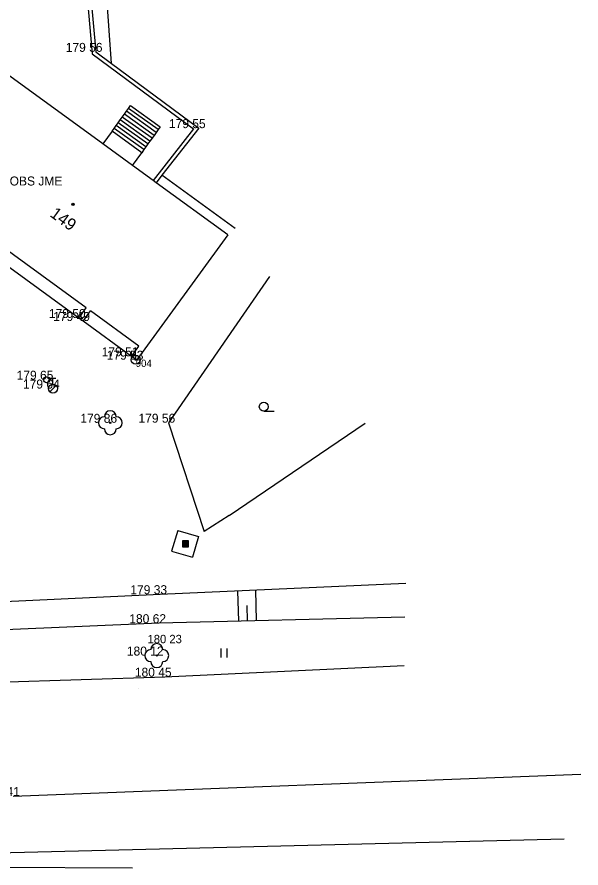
# Model space of a CAD drawing. Extents: x -537755 to -537431, y -1180722 to -1180510.
# Drawn here: x -537478.3 to -537431.3, y -1180722.3 to -1180651.3 of the extents above; entities that cross this region are included whole.
import ezdxf

# ---------------------------------------------------------------- set-up
doc = ezdxf.new("R2010")
doc.units = 0
for name, color, linetype in [('Vrstva 1', 7, 'Continuous'), ('Vrstva 11', 7, 'Continuous'), ('Vrstva 14', 7, 'Continuous'), ('Vrstva 15', 7, 'Continuous'), ('Vrstva 21', 7, 'Continuous'), ('Vrstva 22', 7, 'Continuous'), ('Vrstva 23', 7, 'Continuous'), ('Vrstva 25', 7, 'Continuous'), ('Vrstva 28', 7, 'Continuous'), ('Vrstva 3', 7, 'Continuous'), ('Vrstva 36', 7, 'Continuous'), ('Vrstva 39', 7, 'Continuous'), ('Vrstva 41', 7, 'Continuous'), ('Vrstva 47', 7, 'Continuous'), ('Vrstva 5', 7, 'Continuous'), ('Vrstva 7', 7, 'Continuous'), ('Vrstva 8', 7, 'Continuous')]:
    doc.layers.add(name, color=color, linetype=linetype)

msp = doc.modelspace()

# ---------------------------------------------------------------- linework, layer by layer
at = {"layer": 'Vrstva 1'}
for p, q in [((-537471.77, -1180654.18), (-537471.77, -1180654.18)), ((-537470.39, -1180660.8), (-537470.39, -1180660.8)), ((-537466.39, -1180660.44), (-537466.39, -1180660.44)), ((-537463.16, -1180660.55), (-537463.16, -1180660.55)), ((-537467.93, -1180662.6), (-537467.93, -1180662.6)), ((-537466.25, -1180664.49), (-537466.25, -1180664.49)), ((-537473.18, -1180676.41), (-537473.18, -1180676.41)), ((-537472.82, -1180676.66), (-537472.82, -1180676.66)), ((-537468.77, -1180679.61), (-537468.77, -1180679.61)), ((-537468.35, -1180679.89), (-537468.35, -1180679.89)), ((-537475.87, -1180681.56), (-537475.87, -1180681.56)), ((-537475.34, -1180682.3), (-537475.34, -1180682.3)), ((-537470.55, -1180685.16), (-537470.55, -1180685.16)), ((-537465.7, -1180685.15), (-537465.7, -1180685.15)), ((-537472.94, -1180699.79), (-537472.94, -1180699.79)), ((-537466.378, -1180699.474), (-537466.378, -1180699.474)), ((-537473.04, -1180701.98), (-537473.04, -1180701.98)), ((-537466.466, -1180701.894), (-537466.466, -1180701.894)), ((-537465.11, -1180703.57), (-537465.11, -1180703.57)), ((-537466.67, -1180704.6), (-537466.67, -1180704.6)), ((-537466.003, -1180706.367), (-537466.003, -1180706.367)), ((-537468.22, -1180707.37), (-537468.22, -1180707.37))]:
    msp.add_line(p, q, dxfattribs=at)
at = {"layer": 'Vrstva 11'}
for p, q in [((-537473.149, -1180641.864), (-537472.067, -1180654.346)), ((-537472.067, -1180654.346), (-537463.601, -1180660.61)), ((-537466.899, -1180661.153), (-537469.38, -1180659.384)), ((-537466.729, -1180660.916), (-537469.211, -1180659.146)), ((-537466.56, -1180660.678), (-537469.041, -1180658.908)), ((-537467.407, -1180661.867), (-537469.889, -1180660.097)), ((-537467.238, -1180661.629), (-537469.719, -1180659.859)), ((-537467.068, -1180661.391), (-537469.55, -1180659.622)), ((-537467.746, -1180662.342), (-537470.228, -1180660.573)), ((-537467.577, -1180662.104), (-537470.058, -1180660.335)), ((-537463.601, -1180660.61), (-537466.983, -1180664.922)), ((-537460.141, -1180668.942), (-537466.25, -1180664.49)), ((-537464.922, -1180694.166), (-537463.182, -1180694.658)), ((-537463.182, -1180694.658), (-537463.698, -1180696.382))]:
    msp.add_line(p, q, dxfattribs=at)
for points in [[(-537470.39, -1180660.8), (-537470.228, -1180660.573), (-537470.058, -1180660.335), (-537469.889, -1180660.097), (-537469.719, -1180659.859), (-537469.55, -1180659.622), (-537469.38, -1180659.384), (-537469.211, -1180659.146), (-537469.041, -1180658.908), (-537468.872, -1180658.671), (-537466.39, -1180660.44), (-537466.56, -1180660.678), (-537466.729, -1180660.916), (-537466.899, -1180661.153), (-537467.068, -1180661.391), (-537467.238, -1180661.629), (-537467.407, -1180661.867), (-537467.577, -1180662.104), (-537467.746, -1180662.342), (-537467.93, -1180662.6)], [(-537468.707, -1180663.666), (-537467.93, -1180662.6), (-537470.39, -1180660.8), (-537471.17, -1180661.871)], [(-537464.922, -1180694.166), (-537465.438, -1180695.89), (-537463.698, -1180696.382)]]:
    msp.add_lwpolyline(points, dxfattribs=at)
at = {"layer": 'Vrstva 14'}
for p, q in [((-537466.378, -1180699.474), (-537445.876, -1180698.559)), ((-537486.861, -1180700.435), (-537466.378, -1180699.474)), ((-537445.969, -1180701.386), (-537466.466, -1180701.894)), ((-537466.466, -1180701.894), (-537486.999, -1180702.764)), ((-537466.003, -1180706.367), (-537446.015, -1180705.434)), ((-537483.645, -1180706.944), (-537466.003, -1180706.367)), ((-537478.67, -1180716.34), (-537431.26, -1180714.51)), ((-537432.66, -1180719.92), (-537480.74, -1180721.12)), ((-537500.95, -1180722.15), (-537468.69, -1180722.34))]:
    msp.add_line(p, q, dxfattribs=at)
at = {"layer": 'Vrstva 15'}
for p, q in [((-537459.926, -1180699.186), (-537459.862, -1180701.73)), ((-537458.427, -1180699.119), (-537458.363, -1180701.693)), ((-537459.144, -1180700.431), (-537459.113, -1180701.712))]:
    msp.add_line(p, q, dxfattribs=at)
at = {"layer": 'Vrstva 21'}
for radius in [0.375, 0.05]:
    msp.add_circle((-537468.43, -1180679.89), radius, dxfattribs=at)
at = {"layer": 'Vrstva 22'}
for centre in [(-537470.55, -1180685.16), (-537466.67, -1180704.6)]:
    msp.add_circle(centre, 0.05, dxfattribs=at)
for centre, start, end in [((-537470.55, -1180684.66), 0, 180), ((-537471.05, -1180685.16), 90, 270), ((-537470.05, -1180685.16), 270, 90), ((-537470.55, -1180685.66), 180, 0), ((-537466.67, -1180704.1), 0, 180), ((-537467.17, -1180704.6), 90, 270), ((-537466.17, -1180704.6), 270, 90), ((-537466.67, -1180705.1), 180, 0)]:
    msp.add_arc(centre, 0.5, start, end, dxfattribs=at)
at = {"layer": 'Vrstva 25'}
for points in [[(-537464.517, -1180695.517), (-537464.017, -1180695.517), (-537464.017, -1180695.017), (-537464.517, -1180695.017)], [(-537464.467, -1180695.467), (-537464.067, -1180695.467), (-537464.067, -1180695.067), (-537464.467, -1180695.067)], [(-537464.417, -1180695.417), (-537464.117, -1180695.417), (-537464.117, -1180695.117), (-537464.417, -1180695.117)], [(-537464.367, -1180695.367), (-537464.167, -1180695.367), (-537464.167, -1180695.167), (-537464.367, -1180695.167)], [(-537464.317, -1180695.317), (-537464.217, -1180695.317), (-537464.217, -1180695.217), (-537464.317, -1180695.217)]]:
    msp.add_lwpolyline(points, close=True, dxfattribs=at)
at = {"layer": 'Vrstva 28'}
for p, q in [((-537475.59, -1180681.425), (-537475.09, -1180681.425)), ((-537475.34, -1180681.925), (-537475.34, -1180681.425)), ((-537475.598, -1180682.572), (-537475.068, -1180682.042))]:
    msp.add_line(p, q, dxfattribs=at)
for centre, radius in [((-537475.87, -1180681.56), 0.25), ((-537475.34, -1180682.3), 0.375)]:
    msp.add_circle(centre, radius, dxfattribs=at)
at = {"layer": 'Vrstva 36'}
for p, q in [((-537457.736, -1180684.192), (-537456.861, -1180684.192)), ((-537461.296, -1180704.773), (-537461.296, -1180704.023)), ((-537460.796, -1180704.773), (-537460.796, -1180704.023))]:
    msp.add_line(p, q, dxfattribs=at)
msp.add_circle((-537457.736, -1180683.817), 0.375, dxfattribs=at)
at = {"layer": 'Vrstva 39'}
for radius in [0.09, 0.0398]:
    msp.add_circle((-537473.67, -1180666.92), radius, dxfattribs=at)
at = {"layer": 'Vrstva 5'}
for p, q in [((-537471.17, -1180661.871), (-537479.24, -1180655.98)), ((-537468.707, -1180663.666), (-537471.17, -1180661.871)), ((-537472.568, -1180675.569), (-537481.448, -1180669.099)), ((-537460.746, -1180669.452), (-537468.35, -1180679.89)), ((-537473.18, -1180676.41), (-537482.06, -1180669.94)), ((-537473.18, -1180676.41), (-537472.568, -1180675.569)), ((-537472.82, -1180676.66), (-537472.208, -1180675.819)), ((-537468.158, -1180678.769), (-537472.208, -1180675.819)), ((-537472.82, -1180676.66), (-537473.18, -1180676.41)), ((-537468.77, -1180679.61), (-537472.82, -1180676.66)), ((-537468.77, -1180679.61), (-537468.158, -1180678.769)), ((-537468.35, -1180679.89), (-537468.77, -1180679.61))]:
    msp.add_line(p, q, dxfattribs=at)
for points in [[(-537466.983, -1180664.922), (-537468.707, -1180663.666)], [(-537466.732, -1180665.105), (-537466.983, -1180664.922)], [(-537460.746, -1180669.452), (-537466.732, -1180665.105)]]:
    msp.add_lwpolyline(points, dxfattribs=at)
at = {"layer": 'Vrstva 7'}
for p, q in [((-537470.445, -1180655.161), (-537472.08, -1180632.29)), ((-537472.84, -1180641.84), (-537471.77, -1180654.18)), ((-537471.77, -1180654.18), (-537470.445, -1180655.161)), ((-537470.445, -1180655.161), (-537463.16, -1180660.55)), ((-537463.16, -1180660.55), (-537466.25, -1180664.49)), ((-537466.25, -1180664.49), (-537466.732, -1180665.105)), ((-537457.256, -1180672.939), (-537465.7, -1180685.15)), ((-537465.7, -1180685.15), (-537462.728, -1180694.25)), ((-537460.64, -1180692.9), (-537449.283, -1180685.191))]:
    msp.add_line(p, q, dxfattribs=at)
at = {"layer": 'Vrstva 8'}
msp.add_line((-537460.64, -1180692.9), (-537462.728, -1180694.25), dxfattribs=at)

# ---------------------------------------------------------------- texts
at = {"layer": 'Vrstva 23'}
msp.add_text('904', height=0.6, dxfattribs=at).set_placement((-537468.43, -1180680.49))
at = {"layer": 'Vrstva 3'}
for s, height, p in [('179 56 ', 0.75, (-537474.27, -1180654.18)), ('179 55 ', 0.75, (-537465.66, -1180660.55)), ('179 50 ', 0.75, (-537475.68, -1180676.41)), ('179 49 ', 0.75, (-537475.32, -1180676.66)), ('179 51 ', 0.75, (-537471.27, -1180679.61)), ('179 53 ', 0.75, (-537470.85, -1180679.89)), ('179 65 ', 0.75, (-537478.37, -1180681.56)), ('179 64 ', 0.75, (-537477.84, -1180682.3)), ('179 86 ', 0.75, (-537473.05, -1180685.16)), ('179 56 ', 0.75, (-537468.2, -1180685.15)), ('179 33 ', 0.75, (-537468.878, -1180699.474)), ('180 62 ', 0.75, (-537468.966, -1180701.894)), ('180 23 ', 0.7, (-537467.443, -1180703.57)), ('180 12 ', 0.75, (-537469.17, -1180704.6)), ('180 45 ', 0.75, (-537468.503, -1180706.367)), ('176 41 ', 0.75, (-537481.17, -1180716.34))]:
    msp.add_text(s, height=height, dxfattribs=at).set_placement(p)
at = {"layer": 'Vrstva 41'}
msp.add_text('OBS JME', height=0.75, dxfattribs=at).set_placement((-537478.953, -1180665.341))
at = {"layer": 'Vrstva 47'}
msp.add_text('149', height=1, rotation=323.92278, dxfattribs=at).set_placement((-537475.662, -1180667.874))

doc.saveas('drawing.dxf')
